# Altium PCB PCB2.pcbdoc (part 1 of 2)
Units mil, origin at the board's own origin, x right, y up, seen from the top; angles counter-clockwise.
Board outline 4645 x 3125 mil, 2 copper layers (Top Layer, Bottom Layer); 221 components, 102 nets, 399 pads, 608 vias.
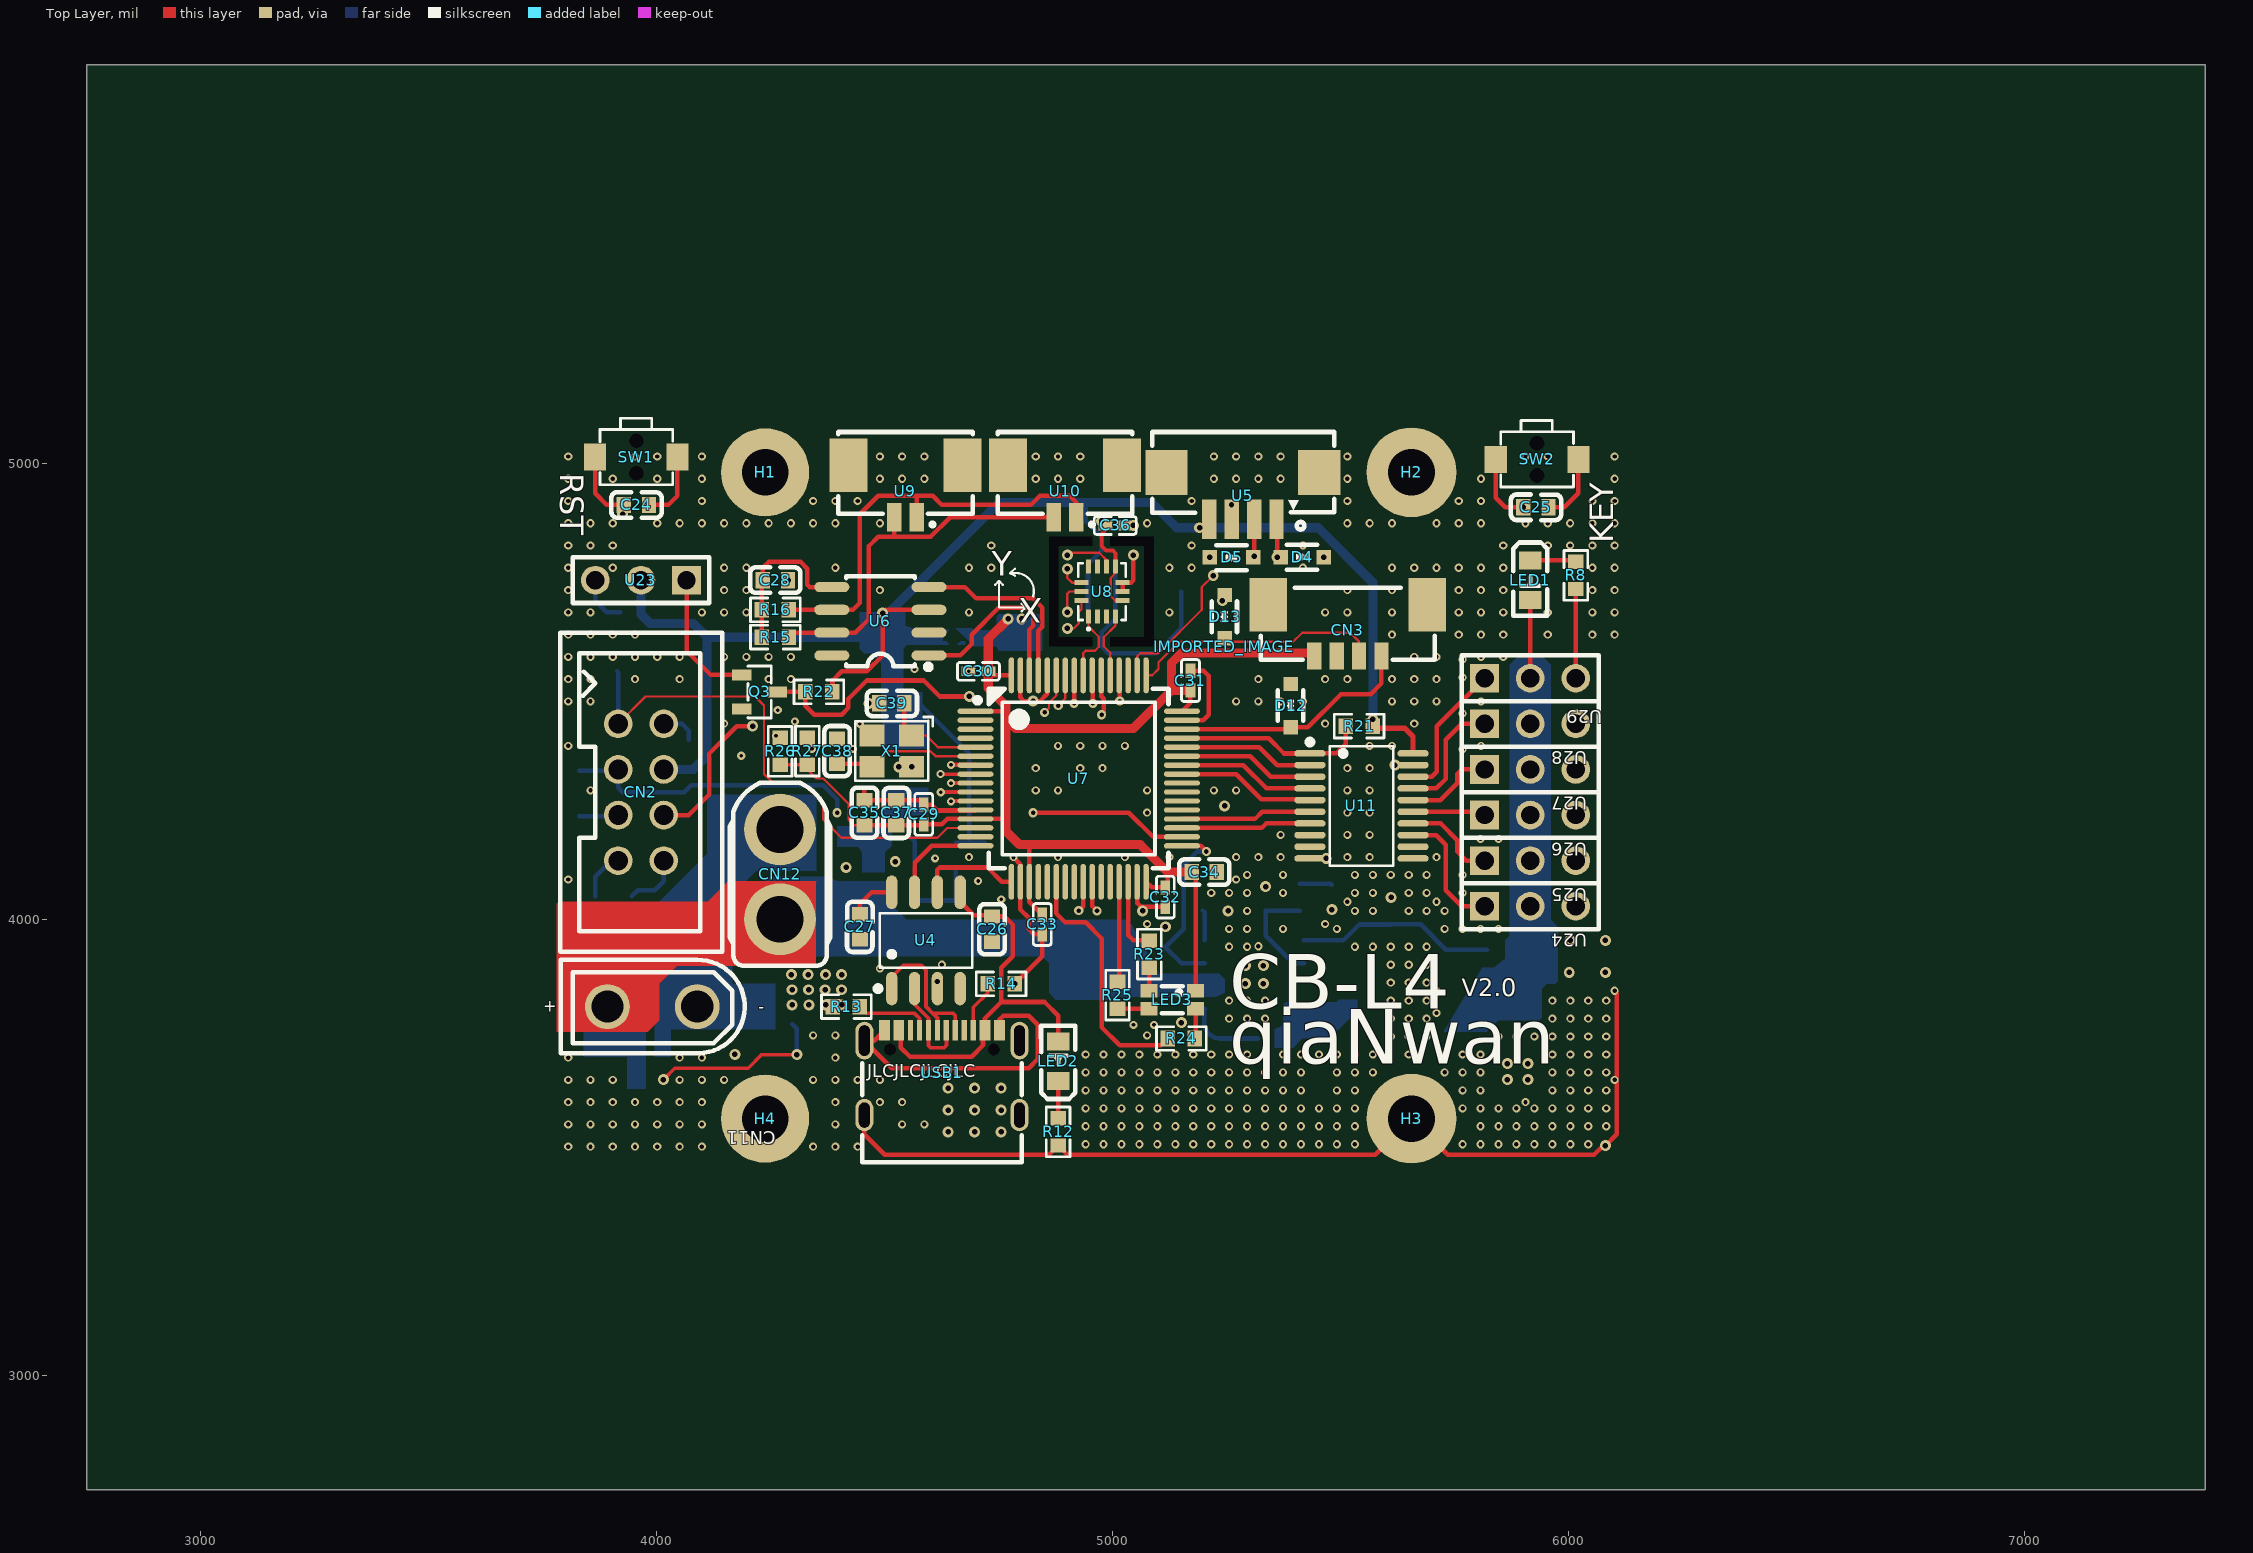
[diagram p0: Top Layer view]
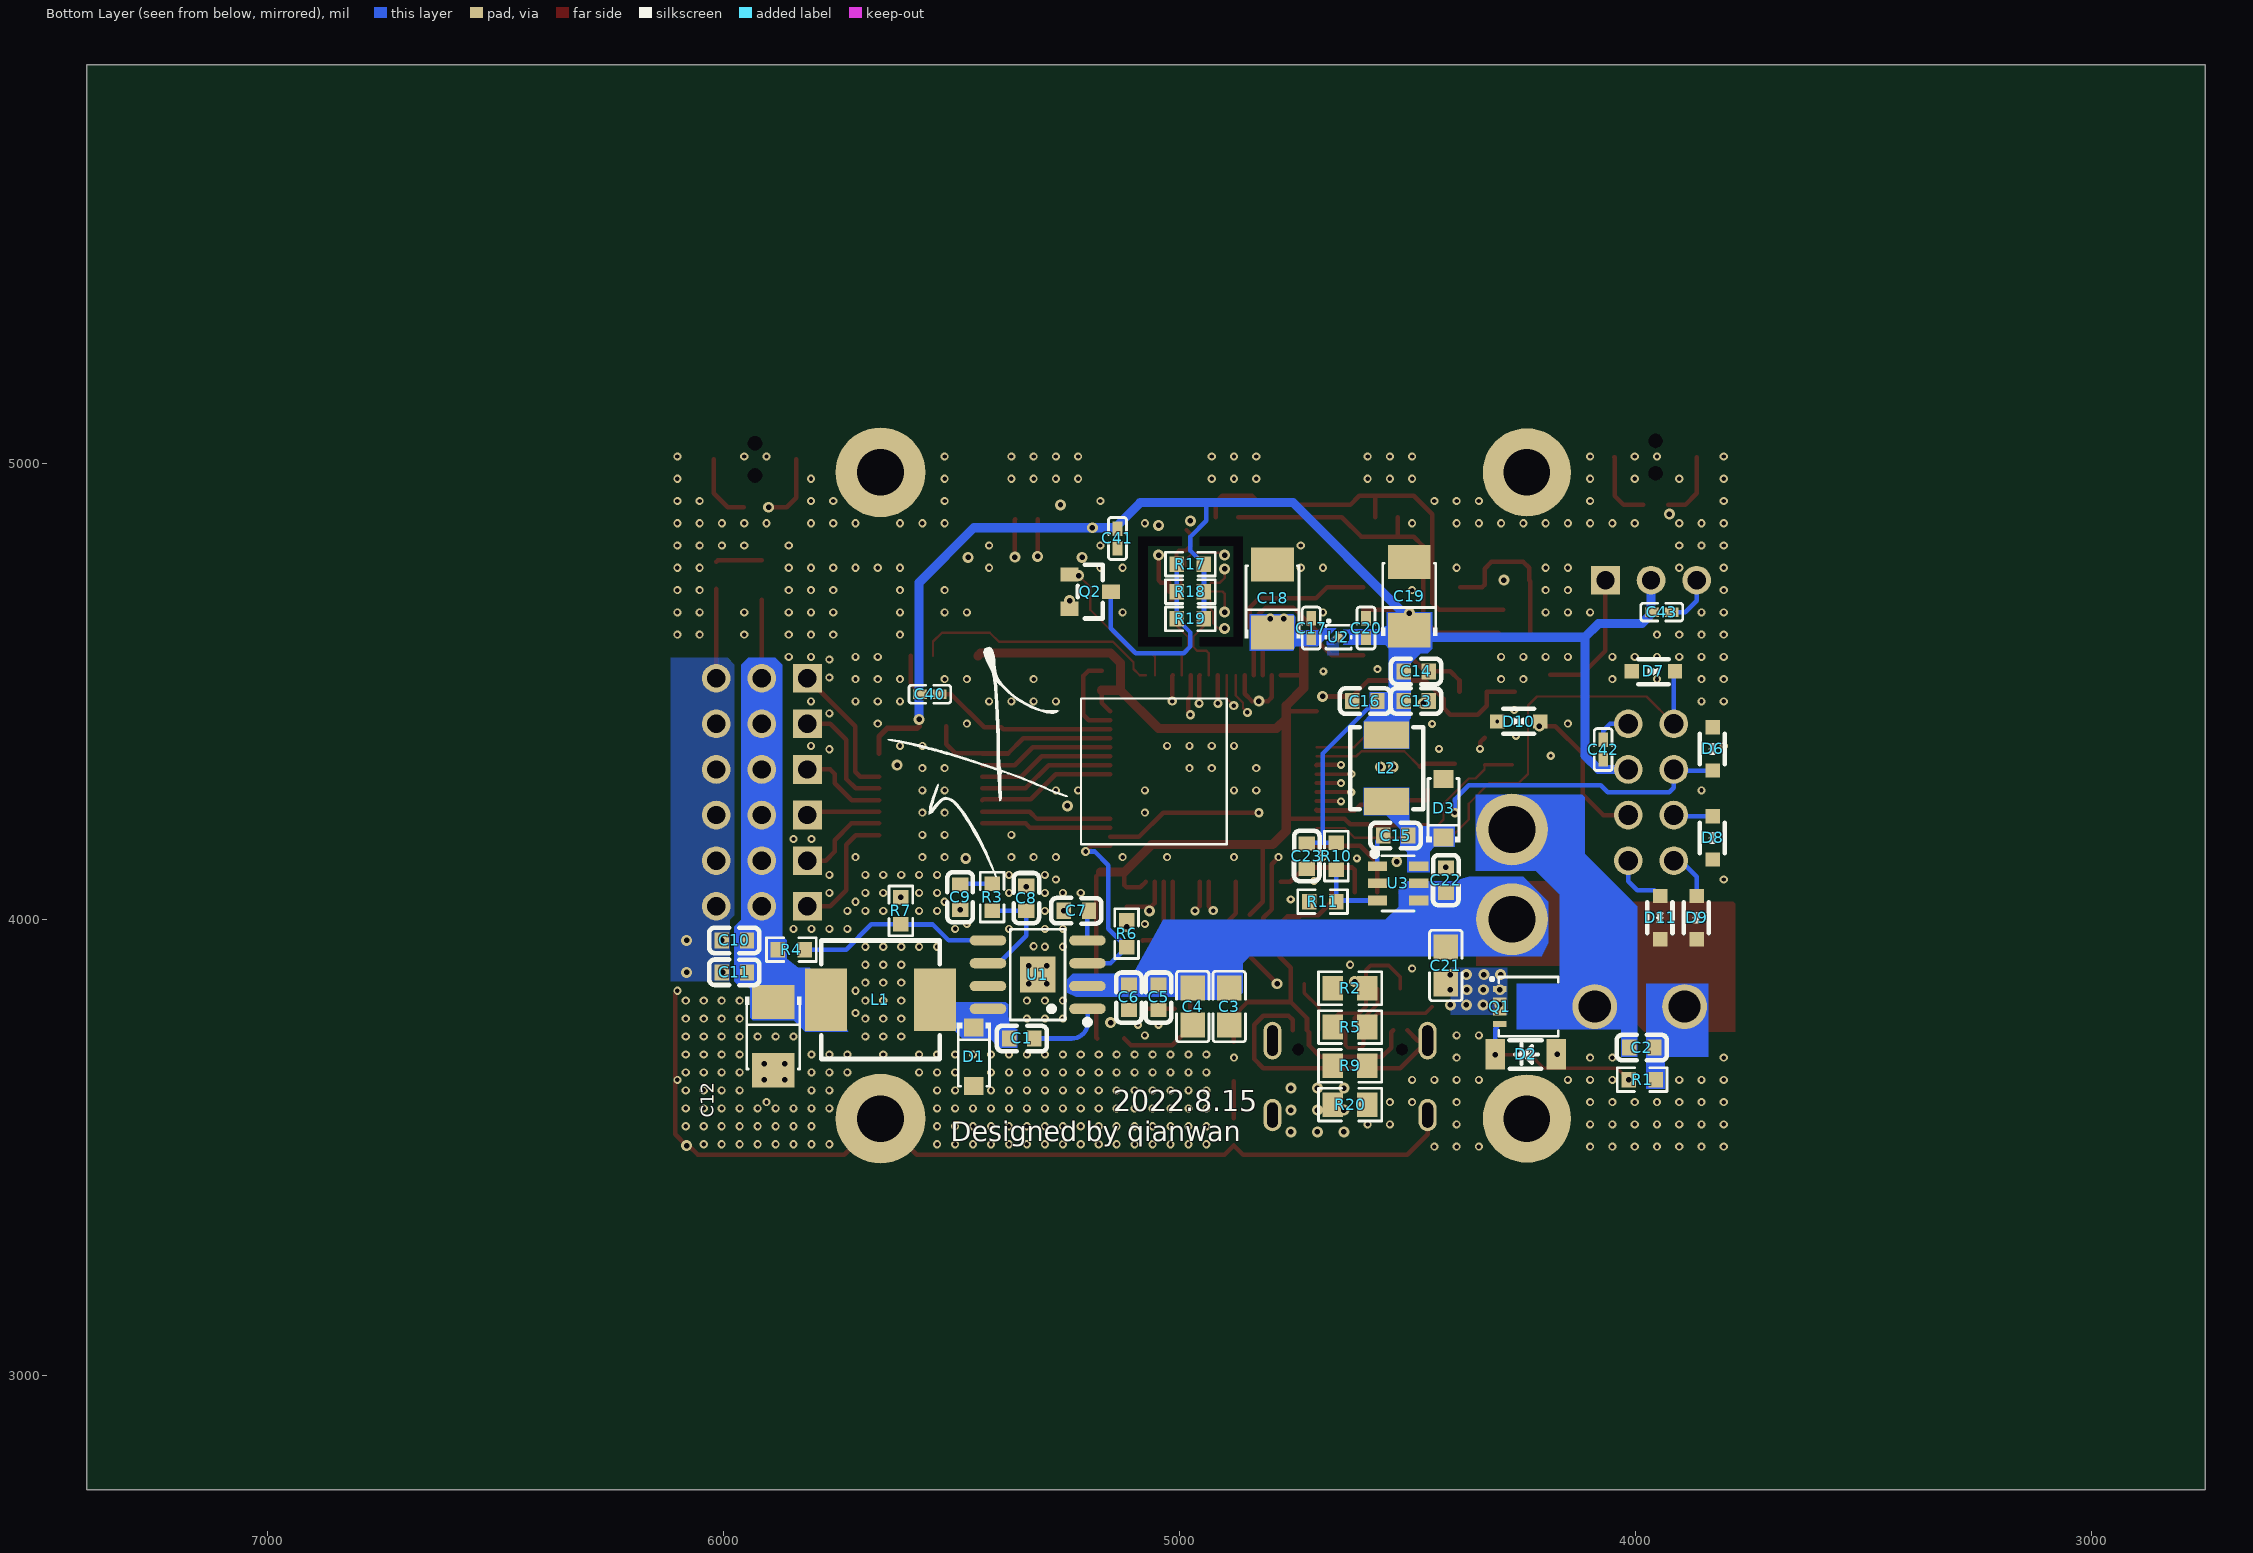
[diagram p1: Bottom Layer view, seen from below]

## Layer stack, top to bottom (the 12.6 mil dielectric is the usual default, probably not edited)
Top Solder: solder mask 0.4, Solder Resist, Dk 3.5
Top Layer: signal copper 1.4
Dielectric 1: dielectric 12.6, FR-4, Dk 4.8
Bottom Layer: signal copper 1.4
Bottom Solder: solder mask 0.4, Solder Resist, Dk 3.5

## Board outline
7395,2750 2750,2750 2750,5875 7395,5875
cut-out: 4955,4600 4955,4620 4880,4620 4880,4820 4955,4820 4955,4840 4860,4840 4860,4600
cut-out: 4994.06,4600 4994.06,4620 5069.06,4620 5069.06,4820 4994.06,4820 4994.06,4840 5089.06,4840 5089.06,4600

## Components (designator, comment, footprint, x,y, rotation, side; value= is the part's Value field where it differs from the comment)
C1 "CC0603KRX7R9BB104" C0603 5345,3740 r0 bottom
C2 "CL10B104KC8NNNC" C0603 3985,3720 r180 bottom
C3 "C3216X5R1V226M160AC" C0805 4890,3810 r90 bottom
C4 "C3216X5R1V226M160AC" C0805 4970,3810 r90 bottom
C5 "CL10B104KC8NNNC" C0603 5045,3830 r90 bottom
C6 "CL10B104KC8NNNC" C0603 5110,3830 r90 bottom
C7 "0603B822J500CT" C0603 5225,4020 r180 bottom
C8 "CC0603GRNPO9BN100" C0603 5335,4047.56 r270 bottom
C9 "CL10B102KB8NNNC" C0603 5480,4050 r90 bottom
C10 "CC0603KRX7R9BB104" C0603 5975,3955 r180 bottom
C11 "CC0603KRX7R9BB104" C0603 5975,3885 r180 bottom
C12 "CA45-B-16V-47uF-K" CAP-SMD_L3.5-W2.8-R-RD 5890,3745 r90 bottom
C13 "ZRB18AR60J226ME01L" C0603 4480,4480 r180 bottom
C14 "ZRB18AR60J226ME01L" C0603 4480,4545 r180 bottom
C15 "CL10B104KC8NNNC" C0603 4525,4185 r180 bottom
C16 "CL10B104KC8NNNC" C0603 4592.44,4480 r0 bottom
C17 "CGA2B3X7R1V104MT0Y0F" C0402 4710,4640 r270 bottom
C18 "TC211B106K025Y" CAP-SMD_L3.5-W2.8-R-RD 4795,4705 r270 bottom
C19 "TC211B106K025Y" CAP-SMD_L3.5-W2.8-R-RD 4495,4710 r270 bottom
C20 "CGA2B3X7R1V104MT0Y0F" C0402 4590,4640 r270 bottom
C21 "C3216X5R1V226M160AC" C0805 4415,3900 r90 bottom
C22 "CL10B104KC8NNNC" C0603 4415,4087.56 r90 bottom
C23 "GCM1885C2A220JA16D" C0603 4720,4140 r270 bottom
C24 "100nF" C0603 3955,4910 r180 top
C25 "100nF" C0603 5927.44,4905 r180 top
C26 "TCC0603X7R104K500CT" C0603 4735,3980 r90 top
C27 "TCC0603X7R104K500CT" C0603 4445,3985 r90 top
C28 "CL10B104KC8NNNC" C0603 4260,4745 r0 top
C29 "GCM155R71C104KA55J" C0402 4585,4231.46 r270 top
C30 "GCM155R71C104KA55J" C0402 4705,4545 r0 top
C31 "GCM155R71C104KA55J" C0402 5170,4525 r270 top
C32 "GCM155R71C104KA55J" C0402 5115,4050 r90 top
C33 "GCM155R71C104KA55J" C0402 4845,3990 r90 top
C34 "GRM188C81E475KE11D" C0603 5200,4105 r180 top
C35 "C0603C103K1RACAUTO" C0603 4455,4235 r270 top
C36 "GCM155R71C104KA55J" C0402 5005,4865 r0 top
C37 "0603F105M160NT" C0603 4525,4235 r90 top
C38 "0603CG200G500NT" C0603 4395,4370 r270 top
C39 "0603CG200G500NT" C0603 4515,4475 r180 top
C40 "GCM155R71C104KA55J" C0402 5546.46,4495 r0 bottom
C41 "GCM155R71C104KA55J" C0402 5135,4836.46 r270 bottom
C42 "GCM155R71C104KA55J" C0402 4070,4373.54 r270 bottom
C43 "GCM155R71C104KA55J" C0402 3941.46,4675 r0 bottom
CN2 "3110-08SG0BK00A1" IDC-TH_3110-08SG0BK00A1 3965,4280 r270 top
CN3 "X9821WVS-04-9TSN" CONN-SMD_4P-P1.25_X9821WVS-04-9TSN 5515,4635 r180 top
CN11 "XT30UPB-M" CONN-TH_XT30UPB-M 3990,3810 r180 top
CN12 "XT30UPB-F" CONN-TH_XT30UPB-F 4270,4100 r90 top
D1 "DSK310" SOD-123_L2.7-W1.8-LS3.7-RD 5450,3700 r270 bottom
D2 "ZMM9V1" LL-34_L3.5-W1.5-RD 4240,3705 r180 bottom
D3 "DSK310" SOD-123_L2.7-W1.8-LS3.7-RD 4420,4245 r90 bottom
D4 "PESD5V0L1BA" SOD-323_L1.7-W1.3-LS2.5-BI 5415,4795 r0 top
D5 "PESD5V0L1BA" SOD-323_L1.7-W1.3-LS2.5-BI 5260,4795 r180 top
D6 "PESD5V0L1BA" SOD-323_L1.7-W1.3-LS2.5-BI 3830,4375 r90 bottom
D7 "PESD5V0L1BA" SOD-323_L1.7-W1.3-LS2.5-BI 3960,4545 r0 bottom
D8 "PESD5V0L1BA" SOD-323_L1.7-W1.3-LS2.5-BI 3830,4180 r90 bottom
D9 "PESD5V0L1BA" SOD-323_L1.7-W1.3-LS2.5-BI 3865,4005 r90 bottom
D10 "PESD5V0L1BA" SOD-323_L1.7-W1.3-LS2.5-BI 4255,4435 r180 bottom
D11 "PESD5V0L1BA" SOD-323_L1.7-W1.3-LS2.5-BI 3945,4005 r90 bottom
D12 "PESD5V0L1BA" SOD-323_L1.7-W1.3-LS2.5-BI 5390,4470 r90 top
D13 "PESD5V0L1BA" SOD-323_L1.7-W1.3-LS2.5-BI 5245,4665 r90 top
H1 "M2.5_M2.5" M2.5#1 4237.44,4981.57 r0 top
H2 "M2.5_M2.5" M2.5#2 5510,4981.57 r0 top
H3 "M2.5_M2.5" M2.5#3 5590,3564.25 r0 top
H4 "M2.5_M2.5" M2.5#1 4237.44,3564.25 r0 top
IMPORTED_IMAGE "IMPORTED_IMAGE" IMPORTED_IMAGE 5243.74,4598.74 r0 top
L1 "SMMS0630-6R8M" IND-SMD_L6.6-W6.6 5655,3825 r0 bottom
L2 "MCS0420-4R7MPN2" IND-SMD_L4.5-W4.0-1 4545,4332.8 r90 bottom
LED1 "NCD0805R1" LED0805-RD_RED 5915,4745 r270 top
LED2 "NCD0805R1" LED0805-RD_RED 4880,3690 r90 top
LED3 "HL-PCF-3216S39FU70GH203BC-A" LED-SMD_4P-L3.2-W1.5-BL 5130,3825 r180 top
Q1 "WSD3066DN33" DFN-8_L3.3-W3.3-P0.65-BL 4265.69,3810.09 r270 bottom
Q2 "AO3400" SOT-23_L2.9-W1.3-P1.90-LS2.4-BR 5195,4720 r0 bottom
Q3 "PMBT3904,235" SOT-23-3_L2.9-W1.3-P1.90-LS2.3-BR-1 4225,4500 r180 top
R1 "AR03BTD1002" R0603 3984.66,3650 r180 bottom
R2 "0805W8F0000T5E" R0805 4625,3850 r0 bottom
R3 "RS-03K473JT" R0603 5410,4050 r90 bottom
R4 "TC0325B4022T5E" R0603 5850,3935 r0 bottom
R5 "0805W8F0000T5E" R0805 4625,3765 r0 bottom
R6 "RG1608P-512-B-T5" R0603 5115,3970 r270 bottom
R7 "RMC06037.68K1%N" R0603 5610,4020 r270 bottom
R8 "RMC06035.1K1%N" R0603 6015,4755.34 r90 top
R9 "0805W8F0000T5E" R0805 4625,3680 r0 bottom
R10 "TC0325B4022T5E" R0603 4655,4140 r90 bottom
R11 "RMC06037.68K1%N" R0603 4685.34,4040 r180 bottom
R12 "RMC06035.1K5%N" R0603 4880,3535 r90 top
R13 "RMC06035.1K1%N" R0603 4415.34,3810 r0 top
R14 "RMC06035.1K1%N" R0603 4755,3860 r180 top
R15 "CR0603JA0560G" R0603 4260,4620 r0 top
R16 "CR0603JA0560G" R0603 4259.66,4680 r0 top
R17 "RTT03121JTP" R0603 4975,4780 r180 bottom
R18 "RTT03121JTP" R0603 4975,4720 r180 bottom
R19 "RTT03121JTP" R0603 4975,4660 r180 bottom
R20 "0805W8F0000T5E" R0805 4625,3595 r0 bottom
R21 "0603WAF1022T5E" R0603 5540,4425 r0 top
R22 "RS-03K512JT" R0603 4355.34,4500 r0 top
R23 "ACPP0603 51R B" R0603 5080,3925 r90 top
R24 "ACPP0603 51R B" R0603 5150,3740 r180 top
R25 "ACPP0603 51R B" R0603 5010,3835 r90 top
R26 "SG73P1JTTD1002F" R0603 4270,4369.66 r270 top
R27 "SG73P1JTTD1002F" R0603 4330,4370 r270 top
SW1 "YD-3410" SW-SMD_L3.9-W2.9-LS4.8-EH-A 3955,5015 r180 top
SW2 "YD-3410" SW-SMD_L3.9-W2.9-LS4.8-EH-A 5930,5010 r180 top
U1 "TPS54531DDAR" SOIC-8_L5.0-W4.0-P1.27-LS6.0-BL-EP2.0 5310,3880 r90 bottom
U2 "SK6019AD4-33" XDFN-4_L1.0-W1.0-P0.65-BL-EP 4650,4620 r270 bottom
U3 "RY8411" SOT-23-6_L2.9-W1.6-P0.95-LS2.8-TL 4519.8,4080 r180 bottom
U4 "CH340N" SOP-8_L4.9-W3.9-P1.27-LS6.0-BL 4590,3955 r0 top
U5 "1.25-4PWTDK" CONN-SMD_4P-P1.25_SHOUHAN_1.25-4PWTDK 5285,4930.16 r180 top
U6 "TJA1040T/CM,118" SOIC-8_L5.0-W4.0-P1.27-LS6.0-BL 4490,4655 r90 top
U7 "STM32L431RCT6" LQFP-64_L10.0-W10.0-P0.50-LS12.0-BL 4925,4310 r270 top
U8 "BMI160" LGA-14_L3.0-W2.5-P0.50-BL 4976.1,4720 r0 top
U9 "1.25-2PWTDK" CONN-SMD_2P-P1.25_SHOU_1.25-2PWTDK 4545,4940 r180 top
U10 "1.25-2PWTDK" CONN-SMD_2P-P1.25_SHOU_1.25-2PWTDK 4895,4940 r180 top
U11 "74HC245PW" TSSOP-20_L6.5-W4.4-P0.65-LS6.4-BL 5545,4250 r270 top
U23 "双塑直脚单排针 3p 19mm" HDR-TH_3P-P2.54-V-M_C9900004029 3965,4745 r0 top
U24 "双塑直脚单排针 3p 19mm" HDR-TH_3P-P2.54-V-M_C9900004029 5915,4030 r180 top
U25 "双塑直脚单排针 3p 19mm" HDR-TH_3P-P2.54-V-M_C9900004029 5915,4130 r180 top
U26 "双塑直脚单排针 3p 19mm" HDR-TH_3P-P2.54-V-M_C9900004029 5915,4230 r180 top
U27 "双塑直脚单排针 3p 19mm" HDR-TH_3P-P2.54-V-M_C9900004029 5915,4330 r180 top
U28 "双塑直脚单排针 3p 19mm" HDR-TH_3P-P2.54-V-M_C9900004029 5915,4430 r180 top
U29 "双塑直脚单排针 3p 19mm" HDR-TH_3P-P2.54-V-M_C9900004029 5915,4530 r180 top
USB1 "TYPE-C 16PIN 3MD(385)" USB-C-SMD_TYPE-C16PIN 4625,3665 r0 top
X1 "X32258MOB4SI" OSC-SMD_4P-L3.2-W2.5-BL 4515,4370 r180 top
? "" ? 0,0 r0 top
? "" ? 0,0 r0 top
? "" ? 0,0 r0 top
? "" ? 0,0 r0 top
? "" ? 0,0 r0 top
? "" ? 0,0 r0 top
? "" ? 0,0 r0 top
? "" ? 0,0 r0 top
? "" ? 0,0 r0 top
? "" ? 0,0 r0 top
? "" ? 0,0 r0 top
? "" ? 0,0 r0 top
? "" ? 0,0 r0 top
? "" ? 0,0 r0 top
? "" ? 0,0 r0 top
? "" ? 0,0 r0 top
? "" ? 0,0 r0 top
? "" ? 0,0 r0 top
? "" ? 0,0 r0 top
? "" ? 0,0 r0 top
? "" ? 0,0 r0 top
? "" ? 0,0 r0 top
? "" ? 0,0 r0 top
? "" ? 0,0 r0 top
? "" ? 0,0 r0 top
? "" ? 0,0 r0 top
? "" ? 0,0 r0 top
? "" ? 0,0 r0 top
? "" ? 0,0 r0 top
? "" ? 0,0 r0 top
? "" ? 0,0 r0 top
? "" ? 0,0 r0 top
? "" ? 0,0 r0 top
? "" ? 0,0 r0 top
? "" ? 0,0 r0 top
? "" ? 0,0 r0 top
? "" ? 0,0 r0 top
? "" ? 0,0 r0 top
? "" ? 0,0 r0 top
? "" ? 0,0 r0 top
? "" ? 0,0 r0 top
? "" ? 0,0 r0 top
? "" ? 0,0 r0 top
? "" ? 0,0 r0 top
? "" ? 0,0 r0 top
? "" ? 0,0 r0 top
? "" ? 0,0 r0 top
? "" ? 0,0 r0 top
? "" ? 0,0 r0 top
? "" ? 0,0 r0 top
? "" ? 0,0 r0 top
? "" ? 0,0 r0 top
? "" ? 0,0 r0 top
? "" ? 0,0 r0 top
? "" ? 0,0 r0 top
? "" ? 0,0 r0 top
? "" ? 0,0 r0 top
? "" ? 0,0 r0 top
? "" ? 0,0 r0 top
? "" ? 0,0 r0 top
? "" ? 0,0 r0 top
? "" ? 0,0 r0 top
? "" ? 0,0 r0 top
? "" ? 0,0 r0 top
? "" ? 0,0 r0 top
? "" ? 0,0 r0 top
? "" ? 0,0 r0 top
? "" ? 0,0 r0 top
? "" ? 0,0 r0 top
? "" ? 0,0 r0 top
? "" ? 0,0 r0 top
? "" ? 0,0 r0 top
? "" ? 0,0 r0 top
? "" ? 0,0 r0 top
? "" ? 0,0 r0 top
? "" ? 0,0 r0 top
? "" ? 0,0 r0 top
? "" ? 0,0 r0 top
? "" ? 0,0 r0 top
? "" ? 0,0 r0 top
? "" ? 0,0 r0 top
? "" ? 0,0 r0 top
? "" ? 0,0 r0 top
? "" ? 0,0 r0 top
? "" ? 0,0 r0 top
? "" ? 0,0 r0 top
? "" ? 0,0 r0 top
? "" ? 0,0 r0 top
? "" ? 0,0 r0 top
? "" ? 0,0 r0 top
? "" ? 0,0 r0 top
? "" ? 0,0 r0 top
? "" ? 0,0 r0 top
? "" ? 0,0 r0 top
? "" ? 0,0 r0 top
? "" ? 0,0 r0 top
? "" ? 0,0 r0 top
? "" ? 0,0 r0 top
? "" ? 0,0 r0 top

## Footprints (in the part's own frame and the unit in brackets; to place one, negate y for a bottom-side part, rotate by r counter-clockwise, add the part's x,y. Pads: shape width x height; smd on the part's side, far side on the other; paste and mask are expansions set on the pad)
C0402 [mm]
  rect 0.79x0.54 smd: 1(-0.545,0) 2(0.545,0)
  silkscreen extent -1.17,-0.5 1.17,0.5
C0603 [mm]
  rect 0.8x0.9 smd: 1(-0.7,0) 2(0.7,0)
  silkscreen extent -1.41,-0.71 1.39,0.72
C0805 [mm]
  rect 1.41x1.35 smd: 1(-1.03,0) 2(1.03,0)
  silkscreen extent -1.96,-0.9 1.96,0.9
CAP-SMD_L3.5-W2.8-R-RD [mil]
  rect 74.8x93.5 smd: 1(74.8,0) 2(-74.7,0)
  silkscreen extent -72,-61 87,61
CONN-SMD_2P-P1.25_SHOU_1.25-2PWTDK [mm]
  rect 0.8x1.6 smd: 1(-0.625,1.45) 2(0.625,1.45)
  rect 2.1x3 smd: 3(3.175,-1.45) 4(-3.175,-1.45)
  silkscreen extent -3.75,-3.3 3.75,1.95
CONN-SMD_4P-P1.25_SHOUHAN_1.25-4PWTDK [mm]
  rect 0.8x2.2 smd: 1(-1.875,1.3) 2(-0.625,1.3) 3(0.625,1.3) 4(1.875,1.3)
  rect 2.35x2.5 smd: 5(4.255,-1.3) 6(-4.255,-1.3)
  silkscreen extent -5.08,-3.55 5.06,1.88
CONN-SMD_4P-P1.25_X9821WVS-04-9TSN [mil]
  rect 31.5x59.1 smd: 1(-73.8,56.1) 2(-24.6,56.1) 3(24.6,56.1) 4(73.8,56.1)
  rect 82.7x118.1 smd: 5(174.2,-56.1) 6(-174.2,-56.1)
  silkscreen extent -191,-94 191,64
CONN-TH_XT30UPB-F [mil]
  round 157.5 hole 102.4: 1(-98.4,0) 2(98.4,0)
  silkscreen extent -201,-110 201,110
CONN-TH_XT30UPB-M [mil]
  round 98.4 hole 70.9: 1(-98.4,0) 2(98.4,0)
  silkscreen extent -202,-102 201,102
DFN-8_L3.3-W3.3-P0.65-BL [mm]
  rect 0.35x0.75 smd: 1(-0.975,-0.78) 2(-0.325,-0.78) 3(0.325,-0.78) 4(0.975,-0.78)
  Top Layer region: -1.222,0.201 -1.222,2.129 -1.174,2.129 -1.174,2.73 -0.773,2.73 -0.773,2.129 -0.524,2.129 -0.524,2.73 -0.123,2.73 -0.123,2.129 0.126,2.129 0.126,2.73 0.528,2.73 0.528,2.129 0.777,2.129 0.777,2.73 0.777,2.129 0.777,2.73 1.178,2.73 1.178,2.129 1.226,2.129 1.226,0.201
  silkscreen extent -1.65,-1.27 1.65,2.46
HDR-TH_3P-P2.54-V-M_C9900004029 [mil]
  rect 63x63 hole 40.2: 1(100,0)
  round 63 hole 40.2: 2(0,0) 3(-100,0)
  silkscreen extent -150,-50 150,50
IDC-TH_3110-08SG0BK00A1 [mil]
  round 63 hole 43.3: 1(-150,-50) 2(-150,50) 3(-50,-50) 4(-50,50) 5(50,-50) 6(50,50) 7(150,-50) 8(150,50)
  silkscreen extent -350,-177 350,178
IMPORTED_IMAGE [mil]
IND-SMD_L4.5-W4.0-1 [mil]
  rect 59.1x98.4 smd: 1(-72.8,0) 2(72.8,0)
  silkscreen extent -90,-80 90,80
IND-SMD_L6.6-W6.6 [mil]
  rect 92.5x137.8 smd: 1(-119.5,0) 2(119.5,0)
  silkscreen extent -130,-130 130,130
LED0805-RD_RED [mm]
  rect 1x1.25 smd: 1(-1.1,0) 2(1.1,0)
  silkscreen extent -2.1,-0.95 1.98,0.96
LED-SMD_4P-L3.2-W1.5-BL [mm]
  rect 0.95x0.75 smd: 1(1.3,-0.5) 2(-1.3,-0.5) 3(-1.3,0.5) 4(1.3,0.5)
  silkscreen extent -0.59,-0.76 0.59,0.75
LGA-14_L3.0-W2.5-P0.50-BL [mm]
  rect 0.28x0.785 smd: 1(-0.75,-1.392) 2(-0.25,-1.392) 3(0.25,-1.392) 4(0.75,-1.392) 8(0.75,1.392) 9(0.25,1.392) 10(-0.25,1.392) 11(-0.75,1.392)
  rect 0.785x0.28 smd: 5(1.142,-0.5) 6(1.142,0) 7(1.142,0.5) 12(-1.142,0.5) 13(-1.142,0) 14(-1.142,-0.5)
  silkscreen extent -1.33,-2.16 1.33,1.58
LL-34_L3.5-W1.5-RD [mil]
  rect 43.3x66.9 smd: 1(-66.9,0) 2(66.9,0)
  silkscreen extent -35,-32 35,32
LQFP-64_L10.0-W10.0-P0.50-LS12.0-BL [mm]
  oval 0.3x2 smd: 1(-3.75,-5.75) 2(-3.25,-5.75) 3(-2.75,-5.75) 4(-2.25,-5.75) 5(-1.75,-5.75) 6(-1.25,-5.75) 7(-0.75,-5.75) 8(-0.25,-5.75) 9(0.25,-5.75) 10(0.75,-5.75) 11(1.25,-5.75) 12(1.75,-5.75) 13(2.25,-5.75) 14(2.75,-5.75) 15(3.25,-5.75) 16(3.75,-5.75) 33(3.75,5.75) 34(3.25,5.75) 35(2.75,5.75) 36(2.25,5.75) 37(1.75,5.75) 38(1.25,5.75) 39(0.75,5.75) 40(0.25,5.75) 41(-0.25,5.75) 42(-0.75,5.75) 43(-1.25,5.75) 44(-1.75,5.75) 45(-2.25,5.75) 46(-2.75,5.75) 47(-3.25,5.75) 48(-3.75,5.75)
  oval 2x0.3 smd: 17(5.75,-3.75) 18(5.75,-3.25) 19(5.75,-2.75) 20(5.75,-2.25) 21(5.75,-1.75) 22(5.75,-1.25) 23(5.75,-0.75) 24(5.75,-0.25) 25(5.75,0.25) 26(5.75,0.75) 27(5.75,1.25) 28(5.75,1.75) 29(5.75,2.25) 30(5.75,2.75) 31(5.75,3.25) 32(5.75,3.75) 49(-5.75,3.75) 50(-5.75,3.25) 51(-5.75,2.75) 52(-5.75,2.25) 53(-5.75,1.75) 54(-5.75,1.25) 55(-5.75,0.75) 56(-5.75,0.25) 57(-5.75,-0.25) 58(-5.75,-0.75) 59(-5.75,-1.25) 60(-5.75,-1.75) 61(-5.75,-2.25) 62(-5.75,-2.75) 63(-5.75,-3.25) 64(-5.75,-3.75)
  silkscreen extent -5,-5.79 5,5
M2.5#1 [mm]
  round 4.9 hole 2.6: 1(0,0)
M2.5#2 [mm]
  round 5 hole 2.6: 1(3.677,0)
M2.5#3 [mm]
  round 5 hole 2.6: 1(1.645,0)
OSC-SMD_4P-L3.2-W2.5-BL [mm]
  rect 1.4x1.2 smd: 1(-1.1,-0.875) 2(1.1,-0.875) 3(1.1,0.875) 4(-1.1,0.875)
  silkscreen extent -2.29,-1.9 2.03,1.65
R0603 [mil]
  rect 31.75x34.02 smd: 1(-29.66,0) 2(29.66,0)
  silkscreen extent -55,-26 55,26
R0805 [mil]
  rect 44.59x54.21 smd: 1(-38.04,0) 2(38.04,0)
  silkscreen extent -69,-36 69,36
SOD-123_L2.7-W1.8-LS3.7-RD [mil]
  rect 39.4x43.3 smd: 1(-64,0) 2(64.1,0)
  silkscreen extent -75,-37 65,37
SOD-323_L1.7-W1.3-LS2.5-BI [mil]
  rect 31.5x31.5 smd: 1(-47.4,0) 2(47.4,0)
  silkscreen extent -34,-27 33,28
SOIC-8_L5.0-W4.0-P1.27-LS6.0-BL [mil]
  oval 22.38x76.78 smd: 1(-75,-106.5) 2(-25,-106.5) 3(25,-106.5) 4(75,-106.5) 5(75,106.5) 6(25,106.5) 7(-25,106.5) 8(-75,106.5)
  silkscreen extent -106,-111 98,75
SOIC-8_L5.0-W4.0-P1.27-LS6.0-BL-EP2.0 [mil]
  oval 22.6x80.2 smd: 1(-75,-109) 2(-25,-109) 3(25,-109) 4(75,-109) 5(75,109) 6(25,109) 7(-25,109) 8(-75,109)
  rect 78.7x78.7 smd: 9(0,0)
  silkscreen extent -110,-115 100,60
SOP-8_L4.9-W3.9-P1.27-LS6.0-BL [mm]
  oval 0.63x1.865 smd: 1(-1.905,-2.682) 2(-0.635,-2.682) 3(0.635,-2.682) 4(1.905,-2.682) 5(1.905,2.682) 6(0.635,2.682) 7(-0.635,2.682) 8(-1.905,2.682)
  silkscreen extent -2.82,-2.83 2.58,1.52
SOT-23-3_L2.9-W1.3-P1.90-LS2.3-BR-1 [mm]
  rect 1.07x0.6 smd: 1(0.99,-0.95) 2(0.99,0.95) 3(-0.99,0)
  silkscreen extent -0.66,-1.45 0.64,1.45
SOT-23-6_L2.9-W1.6-P0.95-LS2.8-TL [mil]
  rect 42.2x20.9 smd: 1(-45.2,37.4) 2(-45.2,0) 3(-45.2,-37.4) 4(45.2,-37.4) 5(45.2,0) 6(45.2,37.4)
  silkscreen extent -57,-61 35,72
SOT-23_L2.9-W1.3-P1.90-LS2.4-BR [mm]
  rect 1x0.8 smd: 1(1.15,-0.95) 2(1.15,0.95) 3(-1.15,0)
  silkscreen extent -0.7,-1.5 0.7,1.5
SW-SMD_L3.9-W2.9-LS4.8-EH-A [mil]
  rect 48.4x59.1 smd: 1(-90.5,0) 2(90.6,0)
  Multi-Layer board cut-out: -15.7,-35.4 -14.15,-42.21 -9.79,-47.67 -3.49,-50.71 3.49,-50.71 9.79,-47.67 14.15,-42.21 15.7,-35.4 15.7,-35.4 14.15,-28.59 9.79,-23.13 3.49,-20.09 -3.49,-20.09 -9.79,-23.13 -14.15,-28.59 -15.7,-35.4
  Multi-Layer board cut-out: -15.7,35.4 -14.15,28.59 -9.79,23.13 -3.49,20.09 3.49,20.09 9.79,23.13 14.15,28.59 15.7,35.4 15.7,35.4 14.15,42.21 9.79,47.67 3.49,50.71 -3.49,50.71 -9.79,47.67 -14.15,42.21 -15.7,35.4
  silkscreen extent -80,-85 80,61
TSSOP-20_L6.5-W4.4-P0.65-LS6.4-BL [mil]
  oval 14.33x68.58 smd: 1(-115.16,-113.03) 2(-89.57,-113.03) 3(-63.98,-113.03) 4(-38.39,-113.03) 5(-12.79,-113.03) 6(12.8,-113.03) 7(38.39,-113.03) 8(63.98,-113.03) 9(89.57,-113.03) 10(115.16,-113.03) 11(115.16,113.03) 12(89.57,113.03) 13(63.98,113.03) 14(38.39,113.03) 15(12.8,113.03) 16(-12.79,113.03) 17(-38.39,113.03) 18(-63.98,113.03) 19(-89.57,113.03) 20(-115.16,113.03)
  silkscreen extent -146,-119 131,70
USB-C-SMD_TYPE-C16PIN [mil]
  oval 39.4x82.7 hole 23.6 slot 66.9 at 90 deg: 1(-170.1,70.4) 2(170.1,70.4)
  oval 39.4x70.9 hole 23.6 slot 55.1 at 90 deg: 3(-170.1,-93) 4(170.1,-93)
  rect 23.6x45.3 smd: A1B12(-126,93) A4B9(-94.5,93) B1A12(126,93) B4A9(94.5,93)
  rect 11.8x45.3 smd: A5(-49.2,93) A6(-9.8,93) A7(9.8,93) A8(-68.9,93) B5(68.9,93) B6(29.5,93) B7(-29.5,93) B8(49.2,93)
  Multi-Layer board cut-out: 126.6,50.7 125.33,56.25 121.78,60.71 116.65,63.18 110.95,63.18 105.82,60.71 102.27,56.25 101,50.7 101,50.7 102.27,45.15 105.82,40.69 110.95,38.22 116.65,38.22 121.78,40.69 125.33,45.15 126.6,50.7
  Multi-Layer board cut-out: -101,50.7 -102.27,56.25 -105.82,60.71 -110.95,63.18 -116.65,63.18 -121.78,60.71 -125.33,56.25 -126.6,50.7 -126.6,50.7 -125.33,45.15 -121.78,40.69 -116.65,38.22 -110.95,38.22 -105.82,40.69 -102.27,45.15 -101,50.7
  silkscreen extent -175,-197 175,20
XDFN-4_L1.0-W1.0-P0.65-BL-EP [mm]
  rect 0.45x0.45 smd rot 45: 5(0,0)
  Top Layer region: 0.425,-0.65 0.225,-0.65 0.225,-0.4 0.375,-0.25 0.425,-0.25
  Top Layer region: -0.425,0.65 -0.225,0.65 -0.225,0.4 -0.375,0.25 -0.425,0.25
  Top Layer region: 0.425,0.65 0.225,0.65 0.225,0.4 0.375,0.25 0.425,0.25
  Top Layer region: -0.225,-0.4 -0.225,-0.65 -0.425,-0.65 -0.425,-0.2 -0.375,-0.25
  silkscreen extent -0.98,-0.7 0.66,0.7
? [mil]

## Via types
v1: diameter 17.76, hole 9.65, Top Layer to Bottom Layer, 499 vias
v2: diameter 24.02, hole 12.01, Top Layer to Bottom Layer, 75 vias
v3: diameter 17.76, hole 8, Top Layer to Bottom Layer, 19 vias
v4: diameter 20, hole 10, Top Layer to Bottom Layer, 11 vias
v5: diameter 24, hole 12, Top Layer to Bottom Layer, 4 vias

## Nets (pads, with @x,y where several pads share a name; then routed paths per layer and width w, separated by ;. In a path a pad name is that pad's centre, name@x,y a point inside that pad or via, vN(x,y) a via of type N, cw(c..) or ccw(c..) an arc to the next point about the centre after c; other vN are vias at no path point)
3V3: C36.1 C37.1 CN3.4 LED3.2 U7.1 U7.13 U7.19 U7.32 U7.48 U8.5 U8.8 | length 3586.1
  Top Layer w5: 4330,4340.34 4330,4330 4350,4310 4365,4310 4420,4255 4420,4220 4432.56,4207.44 4455,4207.44 ; U8.8@5005,4760 4995,4750 4995,4710 5005,4700 5005.31,4700.31 U8.5@5021.08,4700.31
  Top Layer w8: 4270,4340 4329.66,4340 4330,4340.34 ; C36.1@4983.54,4855 4975,4846.46 4975,4820 4985,4810 5000,4810 5005.63,4804.37 U8.8@5005.63,4774.82
  Top Layer w10: 4455,4207.44 C37.1@4525,4207.44 4582.44,4207.44 4585,4210 4625,4210 4636.42,4221.42 U7.13@4698.63,4221.42 4760.95,4221.42 4765,4225.47 ; U7.1@4698.63,4457.64 4764.3,4457.64 4765,4456.94 ; 4726.46,4545 4735.09,4536.37 4777.36,4536.37 ; 4816.73,4164.96 U7.19@4816.73,4083.63 4816.73,4039.73 4845,4011.46 ; U7.32@5072.64,4083.63 5084.81,4071.46 5115,4071.46 5120,4076.46 5120,4105 ; U7.48@5151.37,4457.64 5170,4476.27 5170,4503.54 ; 5172.44,4105 5181.18,4096.26 LED3.2@5181.18,3844.68
  Top Layer w20: v2(4770,4660) 4726.46,4616.46 4726.46,4545 4726.46,4508.54 4765,4470 4765,4456.94 4765,4441.39 ; 5170,4503.54 5128.54,4503.54 ; 5172.44,4105 5120,4105 5060,4165 4795,4165 4765,4195 4765,4225.47 4765,4441.39 ; CN3.4@5441.2,4578.9 5435.1,4585 5150,4585 5128.54,4563.54 5128.54,4503.54 ; 4765,4441.39 4786.39,4420 5045,4420 5128.54,4503.54
  Mid-Layer 2 w10: v2(4800,4660) 4805,4665 4805,4810 4870,4875 v2(4975,4875)
5V: C13.1 C14.1 C16.1 C23.1 C41.1 CN2.4 U5.4 U6.3 U11.20 U23.2 | length 3783.4
  Top Layer w10: 4385,4500 4385,4525 4405,4545 4460,4545 4495,4580 v2(4495,4672.74) 4502.26,4680 U6.3@4596.5,4680
  Top Layer w12: 5569.66,4425 5574.66,4420 5640,4420 5658.03,4401.97 U11.20@5658.03,4365.16
  Bottom Layer w10: 4495,4635.2 4495.2,4635.2 4514.4,4654.4 ; C16.1@4564.88,4480 4570,4480 4685,4365 4685,4170.69 4686.03,4169.66 ; 4655,4169.66 4686.03,4169.66 ; C23.1@4720,4167.56 4717.9,4169.66 4686.03,4169.66 ; 4940,4920 4940,4915 4940,4875.17 4975,4840.17 4975,4809.66 4945.34,4780
  Bottom Layer w12: 4945.34,4660 4945.34,4720 4945.34,4780
  Bottom Layer w20: U23.2@3965,4745 3965,4670 3985,4650 4080,4650 4110,4620 ; CN2.4@4015,4330 4080,4330 4110,4360 4110,4620 ; 4495,4635.2 4479.8,4620 4110,4620 ; 4514.4,4654.4 4514.4,4679.4 4750,4915 4940,4915 5085,4915 5140,4860 v2(5190,4860) 5450,4860 5570,4740 v2(5570,4440)
$1N3621: 
$1N4618: 
$1N5688: 
$1N6767: D2.1 R1.1 | length 386.1
  Top Layer w8: v2(4014.32,3650) 4039.32,3675 4200,3675 4229.7,3704.7 v2(4306.7,3704.7)
  Bottom Layer w10: 4296.38,3771.71 4306.9,3761.19 D2.1@4306.9,3705
$1N6773: C15.1 U3.1 | length 72.8
  Bottom Layer w10: C15.1@4552.56,4185 4565,4172.56 U3.1@4565,4117.4
$1N6774: L2.1
$1N6779:  | length 70.9
  Bottom Layer w10: 5410,4079.66 5477.9,4079.66 5480,4077.56
$1N6780: LED1.1 | length 101.4
  Top Layer w10: LED1.1@5915,4788.31 6011.69,4788.31 6015,4785
$1N6781: U1.8
$1N6783: U1.4 | length 66.5
  Bottom Layer w10: 5197.44,4020 5201,4016.44 U1.4@5201,3955
$1N6785: C1.1 | length 168
  Bottom Layer w10: 5201,3805 ccw(c5201,3804) 5200,3804 5200,3775 ccw(c5235,3775) 5235,3740 C1.1@5317.44,3740
$1N6786: R3.1 U1.6 | length 239
  Bottom Layer w10: R3.1@5410,4020.34 5409.66,4020 5335,4020 5335,3965 5395,3905 U1.6@5419,3905
$1N9912: 
$1N9916: 
$1N9919: 
$1N9922: 
$1N9925: 
$1N9926: 
$1N15560: 
$1N19092: 
$1N19093: 
$1N19102: 
$1N19108: 
$1N20010: 
$1N20185: 
$1N20360: 
$2N2059: USB1.B5 | length 115
  Top Layer w8: USB1.B5@4693.9,3758 4693.9,3808.56 4725.34,3840 4725.34,3860
$2N2060: USB1.A5 | length 167.7
  Top Layer w8: 4445,3810 4460,3795 4565,3795 4575.8,3784.2 USB1.A5@4575.8,3758
$2N2074: LED2.1 | length 82
  Top Layer w10: 4880,3564.66 LED2.1@4880,3646.69
$2N2114: U4.8 | length 103
  Top Layer w10: 4445,4012.56 4445,4035 4470.61,4060.61 U4.8@4515,4060.61
$2N14786: C28.1 R15.1 R16.1 U6.5 | length 352.9
  Top Layer w10: R15.1@4230.34,4620 4230.34,4742.9 C28.1@4232.44,4745 4232.44,4772.44 4245,4785 4315,4785 4330,4770 4330,4735 4335,4730 U6.5@4383.5,4730
$2N14800: R23.1 | length 51.1
  Top Layer w10: 5078.82,3844.68 5080,3845.86 R23.1@5080,3895.34
$2N14801: LED3.3 R24.1 | length 65.9
  Top Layer w10: R24.1@5179.66,3740 5181.18,3741.52 LED3.3@5181.18,3805.32
$2N14802: LED3.4 R25.1 | length 68.8
  Top Layer w10: R25.1@5010,3805.34 LED3.4@5078.82,3805.32
$2N28742: Q2.3 R17.1 R18.1 R19.1 | length 476.2
  Bottom Layer w10: R17.1@5004.66,4780 R18.1@5004.66,4720 R19.1@5004.66,4660 4975,4630.34 4975,4600 4990,4585 5095,4585 5149.72,4639.72 Q2.3@5149.72,4720
$2N33293: U23.1 | length 297.8
  Top Layer w10: U23.1@4065,4745 4065,4590 4117.6,4537.4 4186.02,4537.4
BAT-: C2.1 CN12.2
BMI160_INT1: U7.53 U8.4 | length 145.2
  Top Layer w5: U7.53@4993.9,4536.37 4993.9,4586.1 4980,4600 4980,4620 5005.63,4645.63 U8.4@5005.63,4665.18
BMI160_INT2: U7.52 U8.9 | length 562.7
  Top Layer w5: v2(4900,4800) 4905,4805 4970,4805 4985.94,4789.06 U8.9@4985.94,4774.82
  Top Layer w10: U7.52@5013.58,4536.37 5015,4534.95 v4(5015,4480)
  Mid-Layer 1 w5: v2(4900,4800) 4950,4800 4985,4765 4985,4520 5015,4490 v4(5015,4480)
CAN_H: U6.7 U9.2 U10.2 | length 826.5
  Top Layer w10: 4289.66,4620 4299.66,4630 U6.7@4383.5,4630 4435,4630 4465,4660 4465,4820 4485,4840 4520.96,4840 ; U9.2@4520.39,4882.91 4520.39,4840.56 4520.96,4840 ; U10.2@4870.39,4882.91 4642.91,4882.91 4600,4840 4520.96,4840
CAN_L: U6.6 | length 950.6
  Top Layer w10: 4289.32,4680 U6.6@4383.5,4680 4430,4680 4445,4695 4445,4890 4485,4930 4568.7,4930 ; 4569.6,4882.91 4569.6,4929.1 4568.7,4930 ; 4919.6,4882.91 4919.6,4915.4 4905,4930 4840,4930 4820,4910 4625,4910 4605,4930 4568.7,4930
CAN_RX: U6.4 U7.61 | length 419.3
  Top Layer w10: U6.4@4596.5,4730 4675,4730 4700,4705 4825,4705 4845,4685 4845,4642.37 4836.42,4633.79 U7.61@4836.42,4536.37
CAN_TX: U7.62 | length 427
  Top Layer w10: 4596.5,4580 4665,4580 4690,4605 4690,4625 4750,4685 4810,4685 4825,4670 4825,4645 4816.73,4636.73 U7.62@4816.73,4536.37
DIR: R21.1 U7.45 | length 421
  Top Layer w10: U7.45@5151.37,4398.58 5341.42,4398.58 5375,4365 5431.81,4365 5431.97,4365.16 5490.16,4365.16 5510.34,4385.34 R21.1@5510.34,4425
DN: U4.2 USB1.A7 USB1.B7 | length 214
  Top Layer w8: U4.2@4565,3849.39 4565,3815 4595.5,3784.5 USB1.B7@4595.5,3758 4595.5,3724.5 4600,3720 4630,3720 4635,3725 4635,3757.8 USB1.A7@4634.8,3758
DP: USB1.A6 USB1.B6 | length 341.1
  Top Layer w8: 4515,3849.39 4515,3875 4540,3900 4580,3900 4590,3890 4590,3810 4605.58,3794.42 ; USB1.A6@4615.2,3758 4615.2,3784.8 4605.58,3794.42 ; USB1.B6@4654.5,3758 4654.5,3790.5 4650,3795 4606.17,3795 4605.58,3794.42
FB: R10.1 U3.3 | length 162.4
  Bottom Layer w10: U3.3@4565,4042.6 4653.08,4042.6 4655.68,4040 4655.68,4109.66 R10.1@4655,4110.34
GND: C17.1 C18.2 C19.2 C20.1 C21.1 C24.1 C25.1 C26.1 C27.1 C29.1 C30.1 C31.1 C32.1 C33.1 C34.1 C35.1 C38.1 C40.1 C42.1 C43.1 CN2.2 CN3.3 CN3.5 CN3.6 D3.2 D8.1 D9.1 D10.1 D11.1 H2.1 H3.1 Q1.1 Q1.2 Q1.3 Q3.2 R2.1 R5.1 R9.1 R11.1 R12.1 R13.1 R14.1 R20.1 SW1.1 SW2.1 U3.2 U4.3 U5.3 U5.5 U6.2 U6.8 U7.12 U7.18 U7.31 U7.47 U7.60 U7.63 U8.6 U8.7 U9.3 U9.4 U10.3 U10.4 U11.10 U11.19 USB1.1 USB1.3 USB1.B1A12 X1.2 X1.4 | length 5905.8
  Top Layer w10: C24.1@3982.56,4910 4025,4910 4045,4930 4045,5014.5 SW1.1@4045.5,5015 ; USB1.3@4454.9,3572 4454.9,3530.1 4500,3485 4859.66,3485 R12.1@4880,3505.34 4900.34,3485 5575.51,3485 H3.1@5654.76,3564.25 5734.02,3485 6055,3485 6075,3505 v2(6080,3505) 6105,3530 6105,3644.41 v1(6100.04,3649.37) 6105,3654.33 6105,3839.69 v1(6100.04,3844.65) ; 4455,4285 C35.1@4455,4262.56 4525,4262.56 4575.36,4262.56 C29.1@4585,4252.92 4602.08,4252.92 4615,4240 4697.53,4240 U7.12@4698.63,4241.1 ; 4499,3758 4476.4,3735.4 USB1.1@4454.9,3735.4 4515.3,3675 4815,3675 4835,3695 4835,3770 4815,3790 4760,3790 4751,3781 USB1.B1A12@4751,3758 ; v1(4781.93,4137.56) 4797.05,4122.44 U7.18@4797.05,4083.63 4797.05,4022.95 4815,4005 4815,3980 4826.46,3968.54 C33.1@4845,3968.54 4845,3920.34 R14.1@4784.66,3860 ; U7.63@4797.05,4536.37 4797.05,4487.95 4805,4480 v2(4825,4480) 4840,4480 4856.1,4496.1 U7.60@4856.1,4536.37 ; U8.6@5021.08,4720 U8.7@5021.08,4739.68 5039.68,4739.68 5045,4745 v2(5045,4800) ; U7.31@5052.95,4083.63 5052.95,4037.05 5061.46,4028.54 C32.1@5115,4028.54 ; U7.47@5151.37,4437.95 5197.95,4437.95 5210,4450 5210,4535 5198.54,4546.46 C31.1@5170,4546.46 ; C25.1@5955,4905 5990,4905 6020.5,4935.5 SW2.1@6020.5,5010
  Mid-Layer 1 w10: v2(5045,4800) 4995,4800 4980,4815 4980,4847.46 4997.54,4865 v2(5045,4865)
  Mid-Layer 2 w10: v1(4440.2,3502.91) 4460.48,3482.63 4472.63,3482.63 4475,3485 5575.51,3485 H3.1@5654.76,3564.25
  Bottom Layer w10: 3865,4745 3865,4700 3890,4675 C43.1@3920,4675 ; CN2.2@4015,4430 4055,4430 4070,4415 C42.1@4070,4395
  other v1: 3805.55,3502.91 3854.37,3502.91 3903.19,3502.91 3952.01,3502.91 4000.83,3502.91 4049.65,3502.91 4098.46,3502.91 4342.56,3502.91 4391.38,3502.91 3805.55,3551.73 3854.37,3551.73 3903.19,3551.73 3952.01,3551.73 4000.83,3551.73 4049.65,3551.73 4098.46,3551.73 4391.38,3551.73 4537.83,3551.73 4586.65,3551.73 3805.55,3600.55 3854.37,3600.55 3903.19,3600.55 3952.01,3600.55 4000.83,3600.55 4049.65,3600.55 4098.46,3600.55 4391.38,3600.55 4489.02,3600.55 4537.83,3600.55 5904.76,3600.55 3805.55,3649.37 3854.37,3649.37 3903.19,3649.37 4049.65,3649.37 4098.46,3649.37 4147.28,3649.37 4342.56,3649.37 4391.38,3649.37 4440.2,3649.37 4489.02,3649.37 3805.55,3698.19 4049.65,3698.19 4098.46,3698.19 4391.38,3698.19 4879.57,3698.19 4342.56,3747.01 4391.38,3747.01 5074.84,3747.01 5709.49,3795.83 5709.49,3844.65 4489.02,3893.46 5318.94,3942.28 5074.84,3991.1 5465.39,3991.1 5514.21,4039.92 5709.49,4039.92 3805.55,4088.74 5270.12,4088.74 4684.29,4137.56 4879.57,4137.56 5026.02,4137.56 5123.66,4137.56 5270.12,4137.56 5318.94,4137.56 5367.76,4137.56 5514.21,4137.56 5563.03,4137.56 5709.49,4137.56 5367.76,4186.38 5514.21,4186.38 5563.03,4186.38 5074.84,4235.2 5514.21,4235.2 5563.03,4235.2 3854.37,4284.02 4830.75,4284.02 4879.57,4284.02 5074.84,4284.02 5221.3,4284.02 5270.12,4284.02 5514.21,4284.02 5563.03,4284.02 4830.75,4332.83 4928.39,4332.83 4977.2,4332.83 5514.21,4332.83 5563.03,4332.83 3805.55,4381.65 4879.57,4381.65 4928.39,4381.65 4977.2,4381.65 5026.02,4381.65 5563.03,4381.65 5611.85,4381.65 5807.13,4381.65 4147.28,4430.47 5465.39,4430.47 5660.67,4430.47 3805.55,4479.29 3854.37,4479.29 5270.12,4479.29 5318.94,4479.29 5367.76,4479.29 5416.57,4479.29 5611.85,4479.29 5660.67,4479.29 5709.49,4479.29 5807.13,4479.29 3805.55,4528.11 3854.37,4528.11 3952.01,4528.11 4049.65,4528.11 4244.92,4528.11 4293.74,4528.11 5318.94,4528.11 5465.39,4528.11 5514.21,4528.11 5611.85,4528.11 5660.67,4528.11 5709.49,4528.11 3805.55,4576.93 3854.37,4576.93 3903.19,4576.93 3952.01,4576.93 4000.83,4576.93 4049.65,4576.93 4147.28,4576.93 4196.1,4576.93 4244.92,4576.93 4293.74,4576.93 5660.67,4576.93 5709.49,4576.93 5807.13,4576.93 5855.94,4576.93 3805.55,4625.75 3854.37,4625.75 3903.19,4625.75 3952.01,4625.75 5611.85,4625.75 5758.31,4625.75 5807.13,4625.75 5855.94,4625.75 5953.58,4625.75 6051.22,4625.75 6100.04,4625.75 3805.55,4674.57 3854.37,4674.57 4098.46,4674.57 4147.28,4674.57 4196.1,4674.57 4684.29,4674.57 5123.66,4674.57 5465.39,4674.57 5514.21,4674.57 5611.85,4674.57 5758.31,4674.57 5807.13,4674.57 5855.94,4674.57 5953.58,4674.57 6051.22,4674.57 6100.04,4674.57 3805.55,4723.39 4147.28,4723.39 4196.1,4723.39 4489.02,4723.39 5514.21,4723.39 5611.85,4723.39 5758.31,4723.39 5807.13,4723.39 5855.94,4723.39 6051.22,4723.39 6100.04,4723.39 3805.55,4772.2 3903.19,4772.2 4147.28,4772.2 4196.1,4772.2 4391.38,4772.2 4684.29,4772.2 4733.11,4772.2 5123.66,4772.2 5172.48,4772.2 5416.57,4772.2 5611.85,4772.2 5660.67,4772.2 5709.49,4772.2 5758.31,4772.2 5807.13,4772.2 5855.94,4772.2 6051.22,4772.2 6100.04,4772.2 3805.55,4821.02 3854.37,4821.02 3903.19,4821.02 4733.11,4821.02 5172.48,4821.02 5416.57,4821.02 5855.94,4821.02 5953.58,4821.02 6002.4,4821.02 6051.22,4821.02 6100.04,4821.02 3805.55,4869.84 3854.37,4869.84 3903.19,4869.84 4000.83,4869.84 4049.65,4869.84 4098.46,4869.84 4147.28,4869.84 4196.1,4869.84 4244.92,4869.84 4293.74,4869.84 4342.56,4869.84 4391.38,4869.84 4489.02,4869.84 5074.84,4869.84 5514.21,4869.84 5563.03,4869.84 5611.85,4869.84 5709.49,4869.84 5758.31,4869.84 5807.13,4869.84 5904.76,4869.84 5953.58,4869.84 6002.4,4869.84 6051.22,4869.84 6100.04,4869.84 3805.55,4918.66 4098.46,4918.66 4342.56,4918.66 4391.38,4918.66 4440.2,4918.66 5172.48,4918.66 5514.21,4918.66 5758.31,4918.66 5807.13,4918.66 6051.22,4918.66 6100.04,4918.66 3805.55,4967.48 3903.19,4967.48 4000.83,4967.48 4098.46,4967.48 4489.02,4967.48 4537.83,4967.48 4586.65,4967.48 4830.75,4967.48 4879.57,4967.48 4928.39,4967.48 5221.3,4967.48 5270.12,4967.48 5318.94,4967.48 5367.76,4967.48 5514.21,4967.48 5807.13,4967.48 6100.04,4967.48 3805.55,5016.3 3952.01,5016.3 4000.83,5016.3 4098.46,5016.3 4489.02,5016.3 4537.83,5016.3 4586.65,5016.3 4830.75,5016.3 4879.57,5016.3 4928.39,5016.3 5221.3,5016.3 5270.12,5016.3 5318.94,5016.3 5367.76,5016.3 5514.21,5016.3 5904.76,5016.3 5953.58,5016.3 6100.04,5016.3
  other v2: 4171,3705 5150,3775 4296.38,3813.89 4333.18,3813.89 4370,3813.89 4405,3813.89 4296.38,3846.94 4332.63,3846.94 4368.89,3846.94 4405.14,3846.94 4785,3860 4615,3865 4295,3880 4331.55,3880 4370,3880 4405,3880 5065,4020 4415,4115.12 4522.62,4127.78 5467.73,4134.84 5245,4250 4530.32,4335.55 4558.31,4335.55 5618.37,4339.57 4465,4475 5240,4700 4287.56,4745 5212.6,4795 5462.4,4795 5260,4910
  other v3: 4755,4045 4704.26,4085.28 4610,4135 4185,4360 4430,4375 4445,4430 4302.4,4435 4265,4460 4683.54,4545 4565,4550
I2C1_SCL: 
I2C1_SDA: 
I2C2_SCL: 
I2C2_SDA: 
I2C3_SCL: CN2.6 R26.1 U7.8 | length 860.7
  Top Layer w8: v3(4622.01,4320) 4622.17,4319.84 U7.8@4698.63,4319.84
  Top Layer w10: CN2.6@4015,4230 4070,4230 4115,4275 4115,4365 4175,4425 v2(4210,4425)
  Mid-Layer 2 w10: v2(4210,4425) 4240,4425 4265,4400 4542.01,4400 v3(4622.01,4320)
  other v3: 4261.24,4403.76
I2C3_SDA: R27.1 U7.9 | length 1533.3
  Top Layer w8: v3(4645,4300) 4645.16,4300.16 U7.9@4698.63,4300.16
  Top Layer w10: R27.1@4330,4399.66 4340,4389.66 v3(4340,4375)
  Mid-Layer 2 w10: 4015,4130 3955,4070 3880,4070 3825,4125 3825,4340 3865,4380 4325,4380 4405,4300 v3(4645,4300)
  Bottom Layer w10: 3945,4052.4 3957.6,4065 3995,4065 4015,4085 4015,4130
KEY: U7.26 | length 1650.6
  Top Layer w10: U7.26@4954.53,4083.63 4954.53,4030.47 v4(4965,4020) ; 5839.4,5010 5839.4,4925.6 5860,4905 v2(5899.88,4905)
  Mid-Layer 2 w10: v4(4965,4020) 4965,4250 5535,4820 5815,4820 v2@5895,4900
OSC_IN: C39.1 U7.5 | length 228
  Top Layer w5: 4558.31,4404.45 4590.55,4404.45 4616.1,4378.9 U7.5@4698.63,4378.9
  Top Layer w10: C39.1@4542.56,4475 4542.56,4420.2 4558.31,4404.45
OSC_OUT: U7.6 X1.3 | length 325.2
  Top Layer w5: X1.3@4471.69,4335.55 4506.14,4370 4600,4370 4610.79,4359.21 U7.6@4698.63,4359.21
  Top Layer w10: 4395,4342.44 4464.8,4342.44 X1.3@4471.69,4335.55
PGND: C3.1 C4.1 C5.1 C6.1 C7.1 C8.1 C9.1 C10.1 C11.1 C12.2 D1.2 R6.1 R7.1 R8.1 U1.7 U1.9 USB1.2 USB1.4 | length 195.7
  Top Layer w10: 6015,4530 R8.1@6015,4725.68
  other v1: 4939.96,3508.11 4979.33,3508.11 5018.7,3508.11 5058.07,3508.11 5097.44,3508.11 5136.81,3508.11 5176.18,3508.11 5215.55,3508.11 5254.92,3508.11 5294.29,3508.11 5333.66,3508.11 5373.03,3508.11 5412.4,3508.11 5451.77,3508.11 5491.14,3508.11 5530.51,3508.11 5766.73,3508.11 5806.1,3508.11 5845.47,3508.11 5884.84,3508.11 5924.21,3508.11 5963.58,3508.11 6002.95,3508.11 6042.32,3508.11 4939.96,3547.48 4979.33,3547.48 5018.7,3547.48 5058.07,3547.48 5097.44,3547.48 5136.81,3547.48 5176.18,3547.48 5215.55,3547.48 5254.92,3547.48 5294.29,3547.48 5333.66,3547.48 5373.03,3547.48 5412.4,3547.48 5451.77,3547.48 5491.14,3547.48 5530.51,3547.48 5806.1,3547.48 5845.47,3547.48 5884.84,3547.48 5924.21,3547.48 5963.58,3547.48 6002.95,3547.48 6042.32,3547.48 6081.69,3547.48 4939.96,3586.85 4979.33,3586.85 5018.7,3586.85 5058.07,3586.85 5097.44,3586.85 5136.81,3586.85 5176.18,3586.85 5215.55,3586.85 5254.92,3586.85 5294.29,3586.85 5333.66,3586.85 5373.03,3586.85 5412.4,3586.85 5451.77,3586.85 5491.14,3586.85 5530.51,3586.85 5766.73,3586.85 5806.1,3586.85 5845.47,3586.85 5884.84,3586.85 5924.21,3586.85 5963.58,3586.85 6002.95,3586.85 6042.32,3586.85 6081.69,3586.85 4939.96,3626.22 4979.33,3626.22 5018.7,3626.22 5058.07,3626.22 5097.44,3626.22 5136.81,3626.22 5176.18,3626.22 5215.55,3626.22 5254.92,3626.22 5294.29,3626.22 5333.66,3626.22 5373.03,3626.22 5412.4,3626.22 5491.14,3626.22 5530.51,3626.22 5766.73,3626.22 5806.1,3626.22 5963.58,3626.22 6002.95,3626.22 6042.32,3626.22 6081.69,3626.22 4939.96,3665.59 4979.33,3665.59 5018.7,3665.59 5058.07,3665.59 5097.44,3665.59 5136.81,3665.59 5176.18,3665.59 5215.55,3665.59 5254.92,3665.59 5294.29,3665.59 5333.66,3665.59 5373.03,3665.59 5412.4,3665.59 5491.14,3665.59 5530.51,3665.59 5569.88,3665.59 5727.36,3665.59 5766.73,3665.59 5806.1,3665.59 5963.58,3665.59 6002.95,3665.59 6042.32,3665.59 6081.69,3665.59 4939.96,3704.96 4979.33,3704.96 5018.7,3704.96 5058.07,3704.96 5097.44,3704.96 5136.81,3704.96 5176.18,3704.96 5215.55,3704.96 5254.92,3704.96 5294.29,3704.96 5333.66,3704.96 5373.03,3704.96 5412.4,3704.96 5451.77,3704.96 5491.14,3704.96 5530.51,3704.96 5569.88,3704.96 5648.62,3704.96 5727.36,3704.96 5766.73,3704.96 5806.1,3704.96 5963.58,3704.96 6002.95,3704.96 6042.32,3704.96 6081.69,3704.96 5609.25,3744.33 5648.62,3744.33 5687.99,3744.33 5845.47,3744.33 5884.84,3744.33 5924.21,3744.33 5963.58,3744.33 6002.95,3744.33 6042.32,3744.33 6081.69,3744.33 5254.92,3783.7 5294.29,3783.7 5333.66,3783.7 5609.25,3783.7 5648.62,3783.7 5687.99,3783.7 5963.58,3783.7 6002.95,3783.7 6042.32,3783.7 6081.69,3783.7 5254.92,3823.07 5294.29,3823.07 5333.66,3823.07 5609.25,3823.07 5648.62,3823.07 5687.99,3823.07 5963.58,3823.07 6002.95,3823.07 6042.32,3823.07 6081.69,3823.07 5609.25,3862.44 5648.62,3862.44 5687.99,3862.44 4625,3901.81 5609.25,3901.81 5648.62,3901.81 5687.99,3901.81 5254.92,3941.18 5294.29,3941.18 5530.51,3941.18 5569.88,3941.18 5609.25,3941.18 5648.62,3941.18 5687.99,3941.18 5254.92,3980.55 5294.29,3980.55 5373.03,3980.55 5491.14,3980.55 5727.36,3980.55 5766.73,3980.55 5806.1,3980.55 5845.47,3980.55 5294.29,4019.92 5530.51,4019.92 5569.88,4019.92 5648.62,4019.92 5687.99,4019.92 5727.36,4019.92 5215.55,4059.29 5254.92,4059.29 5294.29,4059.29 5373.03,4059.29 5530.51,4059.29 5569.88,4059.29 5648.62,4059.29 5687.99,4059.29 5766.73,4059.29 5294.29,4098.66 5373.03,4098.66 5530.51,4098.66 5569.88,4098.66 5609.25,4098.66 5648.62,4098.66 5687.99,4098.66 5766.73,4098.66 5806.1,4177.4 5845.47,4177.4 5766.73,4374.25 5766.73,4452.99 5766.73,4531.73 5766.73,4571.1
  other v2: 4638.48,3535 4696.74,3535 4755,3535 4638.48,3583.05 4696.74,3583.05 4755,3583.05 4638.48,3631.11 4696.74,3631.11 4755,3631.11 5865,3650 5910,3650 5865,3685 5910,3685 6000.59,3885 6080,3885 6002.56,3955 6080,3955 5115,3985 5252.56,4020 5480,4022.44 5610,4049.66 5335,4073.15
  other v3: 5045,3770 5090,3770
RST: U7.7 | length 1418.3
  Top Layer w10: 3864.4,5015 3864.4,4935.6 3890,4910 3927.44,4910 ; v3(4645,4340) 4698.16,4340 U7.7@4698.63,4339.53
  Mid-Layer 2 w10: v2(3925,4890) 3925,4870 3955,4840 4575,4840 4645,4770 v3(4645,4340)
SER.1: U11.13 U24.1 | length 280.2
  Top Layer w10: U11.13@5658.03,4186.02 5708.98,4186.02 5730,4165 5730,4065 5765,4030 U24.1@5815,4030
SER.2: U11.14 U25.1 | length 205.4
  Top Layer w10: U11.14@5658.03,4211.61 5718.39,4211.61 5755,4175 5755,4150 5775,4130 U25.1@5815,4130
SER.3: U11.15 U26.1 | length 160
  Top Layer w10: U11.15@5658.03,4237.2 5807.8,4237.2 U26.1@5815,4230
SER.4: U11.16 U27.1 | length 196.5
  Top Layer w10: U11.16@5658.03,4262.79 5717.79,4262.79 5755,4300 5755,4320 5765,4330 U27.1@5815,4330
SER.5: U11.17 U28.1 | length 266
  Top Layer w10: U11.17@5658.03,4288.39 5709.32,4288.39 5730,4309.07 5730,4395 5765,4430 U28.1@5815,4430
SER.5V: L1.2 U24.2 U25.2 U26.2 U27.2 U28.2 U29.2 | length 171.7
  Top Layer w10: U29.2@5915,4530 5915,4701.69
SER.6: U11.18 U29.1 | length 305
  Top Layer w10: U11.18@5658.03,4313.98 5698.98,4313.98 5710,4325 5710,4425 U29.1@5815,4530
SER.7: 
SER.8: 
SERVO_EN: U1.3 U7.33 | length 418
  Top Layer w10: U7.33@5151.37,4162.36 5192.64,4162.36 v4(5205,4150)
  Bottom Layer w10: U1.3@5201,3905 5150.34,3905 5115,3940.34 5155,3980.34 5155,4120 5185,4150 v4(5205,4150)
SPI1_CS: U7.54 U8.12 | length 536.6
  Top Layer w5: v2(4900,4770) 4900,4750 4910.32,4739.68 U8.12@4931.12,4739.68
  Top Layer w10: U7.54@4974.21,4536.37 4974.21,4490.79 4980,4485 4980,4455 v4(4975,4450)
  Mid-Layer 1 w5: v2(4900,4770) 4960,4770 4970,4760 4970,4510 4980,4500 4980,4455 v4(4975,4450)
SPI1_MISO: U7.56 | length 164
  Top Layer w5: U7.56@4934.84,4536.37 4934.84,4584.84 4940,4590 4960,4590 4969,4599 4969,4621 4946.57,4643.43 4946.57,4665.18
SPI1_MOSI: U7.57 U8.14 | length 385.3
  Top Layer w5: v2(4900,4639.29) 4914.29,4639.29 4925,4650 4925,4675 4931.12,4681.12 U8.14@4931.12,4700.31
  Top Layer w10: v4(4915,4475) 4915.16,4475.16 U7.57@4915.16,4536.37
  Mid-Layer 2 w5: v2(4900,4639.29) 4950.71,4639.29 4965,4625 4965,4525 v4(4915,4475)
SPI1_SCL: U7.55 U8.13 | length 416.3
  Top Layer w5: v2(4900,4675) 4900,4715 4905,4720 U8.13@4931.12,4720
  Top Layer w10: U7.55@4954.53,4536.37 4955.96,4534.94 v4(4955.96,4475)
  Mid-Layer 2 w5: v2(4900,4675) 4965,4675 4980,4660 4980,4499.04 v4(4955.96,4475)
